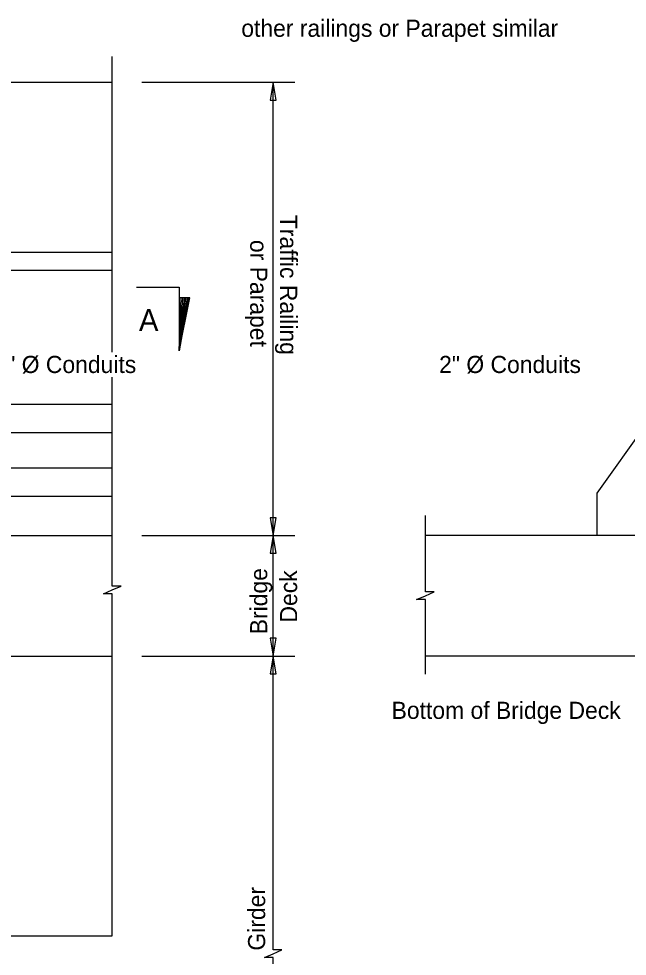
# Model space of a CAD drawing. Extents: x 83976.6 to 84012, y 72958.9 to 72975.6.
# Drawn here: x 83989.96 to 83993.54, y 72963.16 to 72968.67 of the extents above; entities that cross this region are included whole.
import ezdxf

# ---------------------------------------------------------------- set-up
doc = ezdxf.new("R2010")
doc.units = 0
for name, color, linetype in [('Patterning', 7, 'Continuous'), ('PlotBorder_dp', 7, 'Continuous'), ('SheetLines_dp', 7, 'Continuous'), ('SupstrConc', 7, 'Continuous')]:
    doc.layers.add(name, color=color, linetype=linetype)

msp = doc.modelspace()

# ---------------------------------------------------------------- linework, layer by layer
at = {"layer": 'PlotBorder_dp'}
for p, q in [((83990.5104, 72966.4049), (83989.0765, 72966.4049)), ((83990.5104, 72966.2382), (83989.0765, 72966.2382)), ((83990.5104, 72966.0299), (83989.0765, 72966.0299)), ((83990.5104, 72965.8632), (83989.0765, 72965.8632))]:
    msp.add_line(p, q, dxfattribs=at)
at = {"layer": 'SheetLines_dp'}
for p, q in [((83990.6852, 72968.3008), (83991.5851, 72968.3008)), ((83991.4577, 72965.6341), (83991.4577, 72968.3008)), ((83990.9049, 72966.7201), (83990.9532, 72967.0334)), ((83990.9049, 72966.7201), (83990.9157, 72967.0334)), ((83990.9049, 72966.7201), (83990.9257, 72967.0326)), ((83990.9599, 72967.0318), (83990.9049, 72966.7201)), ((83990.9049, 72966.7201), (83990.9441, 72967.0318)), ((83990.9049, 72966.7201), (83990.9349, 72967.0318)), ((83990.6852, 72965.6341), (83991.5851, 72965.6341)), ((83991.4577, 72964.9258), (83991.4577, 72965.6341)), ((83990.6852, 72964.9258), (83991.5851, 72964.9258))]:
    msp.add_line(p, q, dxfattribs=at)
for points in [[(83990.5104, 72966.7134), (83990.5104, 72968.453)], [(83990.6541, 72967.0951), (83990.9049, 72967.0951), (83990.9049, 72966.7201), (83990.9674, 72967.0326), (83990.9049, 72967.0326)], [(83990.5104, 72963.2807), (83990.5104, 72965.2923), (83990.4588, 72965.2923), (83990.5104, 72965.3148), (83990.5621, 72965.3373), (83990.5104, 72965.3373), (83990.5104, 72966.5666)], [(83992.3535, 72964.8197), (83992.3535, 72965.2574), (83992.3018, 72965.2574), (83992.3535, 72965.2799), (83992.4052, 72965.3024), (83992.3535, 72965.3024), (83992.3535, 72965.753)], [(83991.4578, 72962.3289), (83991.4578, 72963.1518), (83991.4061, 72963.1518), (83991.4578, 72963.1743), (83991.5094, 72963.1968), (83991.4578, 72963.1968), (83991.4578, 72964.9257)], [(83982.4439, 72963.2807), (83986.7743, 72963.2807), (83986.7743, 72963.3323), (83986.7968, 72963.2807), (83986.8193, 72963.229), (83986.8193, 72963.2807), (83990.5105, 72963.2807)]]:
    msp.add_lwpolyline(points, dxfattribs=at)
for points in [[(83991.4578, 72968.3007), (83991.4401, 72968.1966), (83991.4754, 72968.1966)], [(83991.4578, 72965.6341), (83991.4754, 72965.7382), (83991.4401, 72965.7382)], [(83991.4578, 72965.6341), (83991.4401, 72965.5299), (83991.4754, 72965.5299)], [(83991.4578, 72964.9257), (83991.4754, 72965.0299), (83991.4401, 72965.0299)], [(83991.4578, 72964.9257), (83991.4401, 72964.8216), (83991.4754, 72964.8216)]]:
    msp.add_lwpolyline(points, close=True, dxfattribs=at)
at = {"layer": 'SupstrConc'}
for p, q in [((83982.4439, 72968.3008), (83990.5104, 72968.3008)), ((83982.4439, 72967.3007), (83990.5104, 72967.3007)), ((83982.4439, 72967.1965), (83990.5104, 72967.1965)), ((83993.3651, 72965.8841), (83993.6533, 72966.2876)), ((83993.3651, 72965.6341), (83993.3651, 72965.8841)), ((83984.828, 72965.6341), (83990.5104, 72965.6341)), ((83994.9068, 72965.6341), (83992.3535, 72965.6341)), ((83984.828, 72964.9258), (83990.5104, 72964.9258)), ((83994.9068, 72964.9258), (83992.3534, 72964.9258))]:
    msp.add_line(p, q, dxfattribs=at)

# ---------------------------------------------------------------- texts
at = {"layer": 'Patterning'}
for s, height, p in [('A', 0.128, (83990.668, 72966.8385)), ('2" Ø Conduits', 0.1008, (83989.8172, 72966.5906)), ('2" Ø Conduits', 0.1008, (83992.4345, 72966.5906)), ('Bottom of Bridge Deck', 0.1008, (83992.1548, 72964.5559))]:
    msp.add_text(s, height=height, dxfattribs=at).set_placement(p)
msp.add_text('Girder', height=0.1008, rotation=90, dxfattribs=at).set_placement((83991.4106, 72963.1928))
at = {"layer": 'SheetLines_dp'}
msp.add_text('other railings or Parapet similar', height=0.1008, dxfattribs=at).set_placement((83991.2701, 72968.5684))
for s, rotation, p in [('Traffic Railing', 270, (83991.4986, 72967.521)), ('or Parapet', 270, (83991.3226, 72967.3737)), ('Bridge', 90, (83991.4228, 72965.0536)), ('Deck', 90, (83991.5988, 72965.1228))]:
    msp.add_text(s, height=0.1008, rotation=rotation, dxfattribs=at).set_placement(p)

doc.saveas('drawing.dxf')
